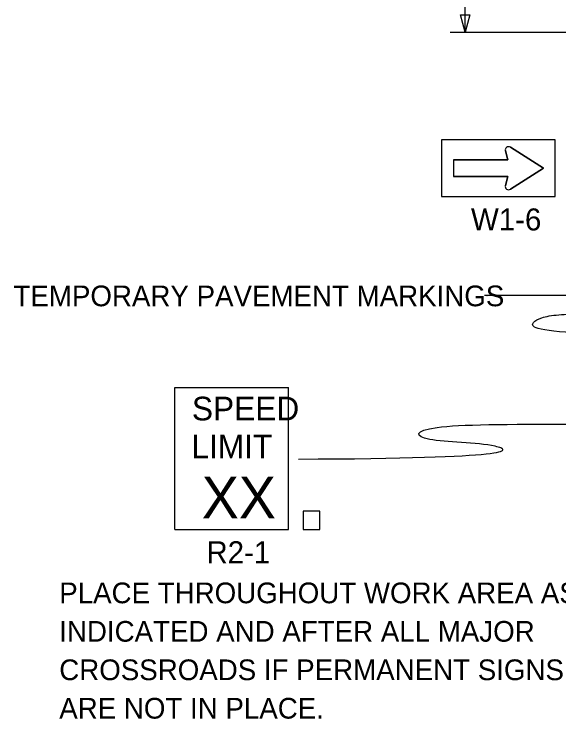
# Model space of a CAD drawing. Extents: x 16752 to 18475, y 7011 to 8262.
# Drawn here: x 16795.2 to 16979.3, y 7642.6 to 7880.9 of the extents above; entities that cross this region are included whole.
import ezdxf

# ---------------------------------------------------------------- set-up
doc = ezdxf.new("R2010")
doc.units = 0
doc.layers.add('TRAFFIC_SIGNS_PR', color=7, linetype='Continuous')
doc.layers.add('TYPICAL_TEXT_DIMEN_PR', color=7, linetype='Continuous')

msp = doc.modelspace()

# ---------------------------------------------------------------- linework, layer by layer
at = {"layer": 'TRAFFIC_SIGNS_PR'}
for p, q in [((16962.92, 7835.86), (16974.08, 7828.76)), ((16962.08, 7831.56), (16961.24, 7834.62)), ((16943.68, 7831.56), (16962.08, 7831.56)), ((16943.68, 7831.56), (16943.68, 7825.96)), ((16974.08, 7828.76), (16962.92, 7821.65)), ((16962.08, 7825.96), (16943.68, 7825.96)), ((16961.24, 7822.9), (16962.08, 7825.96)), ((16849.52, 7754.65), (16887.92, 7754.65)), ((16849.52, 7706.65), (16849.52, 7754.65)), ((16887.92, 7706.65), (16887.92, 7754.65)), ((16849.52, 7706.65), (16887.92, 7706.65))]:
    msp.add_line(p, q, dxfattribs=at)
for points in [[(16939.68, 7819.16), (16978.08, 7819.16), (16978.08, 7838.36), (16939.68, 7838.36)], [(16892.94, 7706.65), (16898.53, 7706.65), (16898.53, 7712.82), (16892.94, 7712.82)]]:
    msp.add_lwpolyline(points, close=True, dxfattribs=at)
for points in [[(16962.92, 7821.65), (16974.08, 7828.76), (16962.92, 7835.86)], [(16961.24, 7834.62), (16962.08, 7831.56), (16943.68, 7831.56), (16943.68, 7825.96), (16962.08, 7825.96), (16961.24, 7822.9)]]:
    msp.add_lwpolyline(points, dxfattribs=at)
for centre, start, end in [((16962.32, 7834.91), 57.5304, 195.3269), ((16962.32, 7834.91), 57.5304, 195.3269), ((16962.32, 7822.6), 164.6731, 302.4696), ((16962.32, 7822.6), 164.6731, 302.4696)]:
    msp.add_arc(centre, 1.12, start, end, dxfattribs=at)
at = {"layer": 'TYPICAL_TEXT_DIMEN_PR'}
for p, q in [((16947.61, 7874.74), (16947.61, 7905.27)), ((16947.61, 7874.74), (16946.04, 7880.6)), ((16946.04, 7880.6), (16947.61, 7880.6)), ((16947.61, 7880.6), (16949.18, 7880.6)), ((16949.18, 7880.6), (16947.61, 7874.74)), ((16942.61, 7874.74), (17027.44, 7874.74))]:
    msp.add_line(p, q, dxfattribs=at)
for points, degree in [([(17055.24, 7771.7), (16970.46, 7771.7), (16970.46, 7779.58), (17006.42, 7779.58), (17006.42, 7785.73), (16958.12, 7785.73), (16954.18, 7785.73)], 2), ([(16891.26, 7730.43), (16965.62, 7730.69), (16962.22, 7736.1), (16930.37, 7736.1), (16930.37, 7742.11), (16961.43, 7742.25), (16984.89, 7742.25)], 3)]:
    msp.add_open_spline(points, degree=degree, dxfattribs=at)

# ---------------------------------------------------------------- texts
at = {"layer": 'TRAFFIC_SIGNS_PR'}
for s, height, p in [('W1-6', 7.44, (16949.62, 7807.72)), ('SPEED', 8, (16855.29, 7743.51)), ('LIMIT', 8, (16855.12, 7730.71)), ('XX', 14.031, (16858.63, 7710.41)), ('R2-1', 7.44, (16860.19, 7695.21)), ('PLACE THROUGHOUT WORK AREA AS', 7, (16810.44, 7681.69)), ('INDICATED AND AFTER ALL MAJOR', 7, (16810.44, 7668.69)), ('CROSSROADS IF PERMANENT SIGNS', 7, (16810.44, 7655.69)), ('ARE NOT IN PLACE.', 7, (16810.44, 7642.69))]:
    msp.add_text(s, height=height, dxfattribs=at).set_placement(p)
at = {"layer": 'TYPICAL_TEXT_DIMEN_PR'}
msp.add_text('TEMPORARY PAVEMENT MARKINGS', height=7, dxfattribs=at).set_placement((16794.97, 7782.1))

doc.saveas('drawing.dxf')
